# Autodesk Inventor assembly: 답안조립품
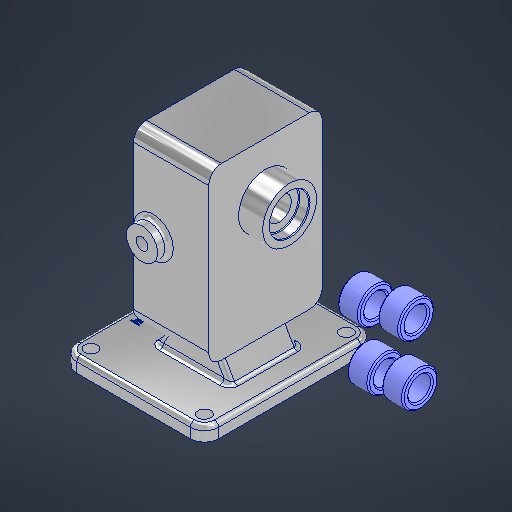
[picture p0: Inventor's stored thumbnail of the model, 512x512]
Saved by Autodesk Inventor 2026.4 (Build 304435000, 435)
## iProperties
Created: 2026-10
Part Number: 답안조립품
Document SubType Name: Assembly
Designer: user
Author: user
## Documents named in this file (3)
- C:\Users\user\Desktop\761003V1009\답안조립품.iam
- C:\Users\user\Desktop\761003V1009\본체.ipt
- C:\Users\user\Desktop\761003V1009\베어링 부시\베어링 부시.ipt
